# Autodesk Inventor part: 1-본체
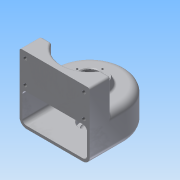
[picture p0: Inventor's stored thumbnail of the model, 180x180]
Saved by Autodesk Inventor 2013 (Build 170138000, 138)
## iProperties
Created: 2015-02
Part Number: 1-본체
Material: 알루미늄 6061
Document SubType Name: Modeling
Designer: MYHOME
Density: 2.40731 g/cm^3
Mass: 511.244 g
Surface Area: 706.56 cm^2
Volume: 212.371 cm^3
Author: MYHOME
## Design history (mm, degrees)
sketch "스케치1"
  geometry: L1 (50, 0)-(50, -50); L2 (-50, 0)-(-50, -50); L3 (-50, -50)-(50, -50); A1 r 50 centre (0, 0) between (50, 0) and (-50, 0); 1 further point
  constraints: 6 end point, 2 point on circle, 2 tangent, 1 centre point, 1 coincident, 1 horizontal, 1 parallel, 1 vertical
  dimensions: "d0" = 50 radius of A1; "d2" = 50 distance of L1.start L1.end
extrude "돌출1" new body sketch "스케치1" distance "d3" = 50; taper "d4" = 0 deg
feature "쉘1" dims "d10" = 4
sketch "스케치2"
  geometry: L1 (-50, 0)-(-50, -50) reference; L2 (-50, -50)-(50, -50) reference; L3 (50, -50)-(50, 0) reference; L4 (-50, -20)-(-34.641, -20); L5 (34.641, -20)-(50, -20); A1 r 50 centre (0, 0) between (50, 0) and (-50, 0) reference; A2 r 40 centre (0, 0) between (-34.641, -20) and (34.641, -20)
  constraints: 4 end point, 2 perpendicular, 2 point on circle, 2 point on line, 1 centre point, 1 coincident, 1 collinear
  dimensions: "d5" = 40 radius of A2; "d7" = 30 distance between parallel lines of L2 L4
extrude "돌출2" join sketch "스케치2" distance "d8" = 45; taper "d9" = 0 deg
sketch "스케치3"
  geometry: C1 r 25 at (0, 0); A1 r 40 centre (0, 0) between (-34.641, -20) and (34.641, -20) reference
  constraints: 1 centre point, 1 coincident
  dimensions: "d11" = 50 diameter of C1
extrude "돌출3" join sketch "스케치3" distance "d13" = 10; taper "d14" = -20 deg
hole "구멍1" diameter "d17" = 20; stored, may be unused: countersink angle "d21" = 90 deg, drill point angle "d23" = 0 deg; dims "d15" = 10, "d16" = 10, "d18" = 6, "d19" = 28, "d20" = 10, "d22" = 14
sketch "스케치4"
  geometry: C1 r 20 at (0, 0); A1 r 50 centre (0, 0) between (50, 0) and (-50, 0) reference
  constraints: 1 centre point, 1 coincident
  dimensions: "d24" = 40 diameter of C1
extrude "돌출4" join sketch "스케치4" distance "d26" = 9; taper "d27" = 0 deg
sketch "스케치5"
  geometry: A1 r 46 centre (0, 0) between (46, 0) and (-46, 0) reference; 1 further point
  constraints: 1 coincident
hole "구멍2" sketch "스케치5" at (0, 0) diameter "d28" = 20; stored, may be unused: countersink angle "d32" = 90 deg, drill point angle "d34" = 0 deg; dims "d29" = 6, "d30" = 28, "d31" = 8, "d33" = 10
sketch "스케치6"
  geometry: L1 (0, 95)-(100, 95) reference; L2 (8.25, 86)-(91.75, 86); L3 (91.75, 86)-(91.75, 53); L4 (91.75, 53)-(8.25, 53); L5 (8.25, 53)-(8.25, 86); L6 (8.25, 86)-(91.75, 53); L7 (91.75, 86)-(8.25, 53); 8 further points
  constraints: 12 end point, 4 coincident, 4 midpoint, 2 parallel, 1 horizontal, 1 perpendicular, 1 vertical alignment
  dimensions: "d35" = 83.5 distance of L2.start L2.end; "d37" = 33 distance of L4.end L2.start; "d38" = 9 distance between parallel lines of L2 L1
hole "구멍3" sketch "스케치6" at (8.25, 86), (91.75, 86), (91.75, 53), (8.25, 53) diameter "d39" = 5.134; stored, may be unused: countersink angle "d43" = 90 deg, drill point angle "d45" = 118 deg; dims "d40" = 10, "d41" = 28, "d42" = 8, "d44" = 13
sketch "스케치7"
  geometry: C1 r 14 at (0, 0) reference; C2 r 21.36 at (0, 0) reference; A1 r 18 centre (0, 0) between (0, 18) and (18, 0); 2 further points
  constraints: 4 point on circle, 2 horizontal alignment, 2 vertical alignment, 1 centre point, 1 coincident
  dimensions: "d46" = 36 diameter of A1
hole "구멍4" sketch "스케치7" at (0, 18), (18, 0), (-18, 0), (0, -18) diameter "d48" = 2.459; stored, may be unused: countersink angle "d52" = 90 deg, drill point angle "d54" = 118 deg; dims "d49" = 6, "d50" = 28, "d51" = 8, "d53" = 9
node "작업 평면1"
sketch "스케치8"
  geometry: L1 (0, 0)-(-100, 0) reference; 3 further points
  constraints: 1 midpoint, 1 vertical alignment, 1 other
  dimensions: "d56" = 25 distance from line of L1 point (-50, 25)
feature "엠보싱1" sketch "스케치8" dims "d0" = 50, "d2" = 50, "d57" = 0.5, "d58" = 0
fillet "모깎기1" dims "d59" = 10, "d60" = 6, "d61" = 0.3
fillet "모깎기2" dims "d62" = 3
fillet "모깎기3" dims "d63" = 3
fillet "모깎기4" dims "d64" = 3
chamfer "모따기1" distance "d65" = 1; stored, may be unused: second distance "d66" = 2, angle "d67" = 45 deg
node "솔리드1"
